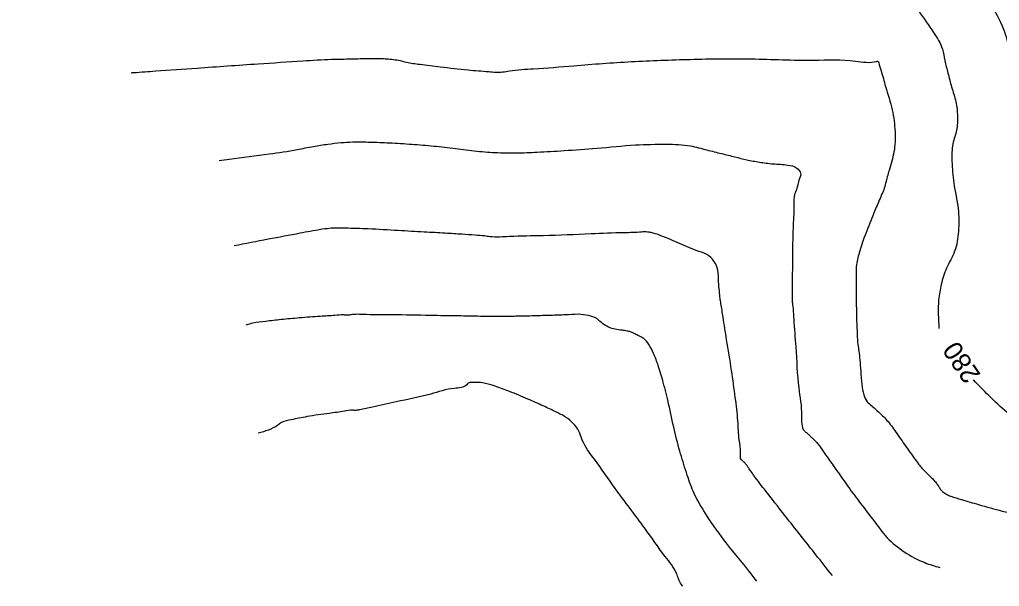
# Model space of a CAD drawing. Extents: x -478102 to -473059, y -1117705 to -1114104.
# Drawn here: x -475379.9 to -475174.1, y -1116864.7 to -1116745.7 of the extents above; entities that cross this region are included whole.
import ezdxf

# ---------------------------------------------------------------- set-up
doc = ezdxf.new("R2010")
doc.units = 0
for name, color, linetype in [('Vrstevnice_hlavni', 7, 'Continuous'), ('Vrstevnice_popis', 7, 'Continuous'), ('Vrstevnice_vedlejsi', 7, 'Continuous')]:
    doc.layers.add(name, color=color, linetype=linetype)

msp = doc.modelspace()

# ---------------------------------------------------------------- linework, layer by layer
at = {"layer": 'Vrstevnice_hlavni'}
for points in [[(-475358.768, -1116741.356), (-475356.711, -1116740.135), (-475352.511, -1116739.455), (-475345.14, -1116738.707), (-475334.598, -1116737.89), (-475327.036, -1116737.27), (-475322.455, -1116736.846), (-475320.855, -1116736.618), (-475319.542, -1116736.519), (-475318.516, -1116736.548), (-475317.776, -1116736.705), (-475315.973, -1116736.853), (-475313.107, -1116736.991), (-475309.177, -1116737.119), (-475304.857, -1116737.63), (-475300.147, -1116738.524), (-475295.047, -1116739.801), (-475290.514, -1116740.779), (-475286.548, -1116741.458), (-475283.15, -1116741.838), (-475278.27, -1116741.681), (-475271.909, -1116740.985), (-475264.066, -1116739.751), (-475256.944, -1116738.794), (-475250.543, -1116738.116), (-475244.862, -1116737.714), (-475239.016, -1116737.489), (-475233.004, -1116737.442), (-475226.827, -1116737.571), (-475220.399, -1116737.105), (-475213.723, -1116736.045), (-475206.796, -1116734.39), (-475200.704, -1116735.146), (-475195.447, -1116738.313), (-475191.025, -1116743.89), (-475187.9, -1116748.412), (-475186.073, -1116751.876), (-475185.543, -1116754.284), (-475184.893, -1116756.934), (-475184.122, -1116759.824), (-475183.231, -1116762.956), (-475182.889, -1116765.987), (-475183.096, -1116768.918), (-475183.853, -1116771.747), (-475184.048, -1116775.433), (-475183.681, -1116779.975), (-475182.751, -1116785.373), (-475182.693, -1116790.16), (-475183.506, -1116794.333), (-475185.19, -1116797.895), (-475186.303, -1116801.281), (-475186.846, -1116804.493), (-475186.791, -1116810.568)], [(-475240.627, -1116864.663), (-475240.877, -1116864.261), (-475241.474, -1116863.11), (-475241.915, -1116861.944), (-475244.28, -1116858.392), (-475248.569, -1116852.455), (-475254.782, -1116844.132), (-475259.162, -1116837.963), (-475261.708, -1116833.946), (-475262.421, -1116832.082), (-475263.583, -1116830.477), (-475265.193, -1116829.129), (-475267.253, -1116828.04), (-475269.903, -1116826.78), (-475273.143, -1116825.349), (-475276.975, -1116823.747), (-475280.033, -1116822.629), (-475282.318, -1116821.995), (-475283.831, -1116821.845), (-475284.941, -1116821.853), (-475285.647, -1116822.019), (-475285.951, -1116822.343), (-475288.578, -1116823.103), (-475293.529, -1116824.298), (-475300.804, -1116825.929), (-475305.786, -1116827.036), (-475308.475, -1116827.62), (-475308.87, -1116827.681), (-475309.242, -1116827.712), (-475309.59, -1116827.712), (-475309.914, -1116827.682), (-475311.671, -1116827.892), (-475314.861, -1116828.344), (-475319.483, -1116829.037), (-475322.825, -1116829.686), (-475324.887, -1116830.289), (-475325.669, -1116830.847), (-475329.759, -1116832.513)], [(-475165.151, -1116831.586), (-475166.683, -1116831.906), (-475168.964, -1116830.907), (-475171.993, -1116828.59), (-475179.549, -1116821.317)]]:
    msp.add_spline(points, degree=3, dxfattribs=at)
at = {"layer": 'Vrstevnice_vedlejsi'}
for points in [[(-475317.402, -1116697.311), (-475317.363, -1116697.318), (-475316.603, -1116697.461), (-475315.123, -1116697.741), (-475312.92, -1116698.158), (-475311.368, -1116698.443), (-475310.465, -1116698.595), (-475310.211, -1116698.614), (-475309.863, -1116698.624), (-475309.421, -1116698.624), (-475308.884, -1116698.614), (-475308.515, -1116698.664), (-475308.313, -1116698.772), (-475308.278, -1116698.939), (-475308.258, -1116699.23), (-475308.253, -1116699.645), (-475308.262, -1116700.184), (-475308.28, -1116700.605), (-475308.307, -1116700.906), (-475308.342, -1116701.089), (-475308.4, -1116701.257), (-475308.48, -1116701.41), (-475308.582, -1116701.549), (-475308.36, -1116701.763), (-475307.813, -1116702.053), (-475306.941, -1116702.417), (-475305.165, -1116702.522), (-475302.486, -1116702.367), (-475298.904, -1116701.952), (-475295.98, -1116701.58), (-475293.714, -1116701.252), (-475292.107, -1116700.966), (-475290.151, -1116700.632), (-475287.845, -1116700.251), (-475285.19, -1116699.821), (-475283.467, -1116699.685), (-475282.678, -1116699.841), (-475282.82, -1116700.289), (-475282.893, -1116700.598), (-475282.897, -1116700.766), (-475282.83, -1116700.795), (-475282.522, -1116701.008), (-475281.973, -1116701.407), (-475281.183, -1116701.991), (-475279.14, -1116702.532), (-475275.844, -1116703.031), (-475271.295, -1116703.488), (-475267.025, -1116703.455), (-475263.034, -1116702.933), (-475259.323, -1116701.922), (-475255.577, -1116701.148), (-475251.797, -1116700.612), (-475247.981, -1116700.314), (-475244.648, -1116700.178), (-475241.797, -1116700.205), (-475239.43, -1116700.396), (-475236.373, -1116700.194), (-475232.627, -1116699.601), (-475228.192, -1116698.615), (-475224.557, -1116697.628), (-475221.724, -1116696.639), (-475219.691, -1116695.649), (-475215.891, -1116694.546), (-475210.322, -1116693.329), (-475202.985, -1116691.999), (-475196.288, -1116692.148), (-475190.231, -1116693.775), (-475184.814, -1116696.881), (-475179.571, -1116702.762), (-475174.503, -1116711.419), (-475169.608, -1116722.851), (-475165.925, -1116731.003), (-475163.453, -1116735.874), (-475162.192, -1116737.464), (-475161.091, -1116739.704), (-475160.152, -1116742.593), (-475159.374, -1116746.131), (-475155.571, -1116749.024), (-475148.745, -1116751.271), (-475138.894, -1116752.873), (-475131.322, -1116754.29), (-475126.028, -1116755.521), (-475123.014, -1116756.568), (-475119.062, -1116755.588), (-475114.17, -1116752.58), (-475108.341, -1116747.546), (-475101.953, -1116742.021), (-475095.007, -1116736.008), (-475087.504, -1116729.505), (-475082.315, -1116724.914), (-475079.441, -1116722.237), (-475078.882, -1116721.473), (-475078.472, -1116720.916), (-475078.209, -1116720.564), (-475078.094, -1116720.42), (-475077.919, -1116720.217), (-475077.682, -1116719.958)], [(-475170.121, -1116764.984), (-475169.8, -1116763.784), (-475169.712, -1116762.54), (-475169.857, -1116761.254), (-475170.235, -1116759.926), (-475170.837, -1116757.447), (-475171.664, -1116753.818), (-475172.715, -1116749.04), (-475175.186, -1116743.622), (-475179.076, -1116737.565), (-475184.386, -1116730.868), (-475188.402, -1116725.291), (-475191.125, -1116720.833), (-475192.554, -1116717.494), (-475194.034, -1116714.966), (-475195.565, -1116713.248), (-475197.147, -1116712.341), (-475198.916, -1116711.866), (-475200.872, -1116711.823), (-475203.014, -1116712.211), (-475204.641, -1116712.566), (-475205.751, -1116712.889), (-475206.344, -1116713.178), (-475210.286, -1116714.159), (-475217.576, -1116715.832), (-475228.214, -1116718.196), (-475235.384, -1116719.766), (-475239.087, -1116720.542), (-475239.321, -1116720.523), (-475239.604, -1116720.52), (-475239.934, -1116720.534), (-475240.312, -1116720.563), (-475241.346, -1116720.796), (-475243.034, -1116721.231), (-475245.377, -1116721.87), (-475250.485, -1116722.853), (-475258.355, -1116724.181), (-475268.989, -1116725.854), (-475276.404, -1116726.933), (-475280.601, -1116727.418), (-475281.579, -1116727.309), (-475284.618, -1116726.638), (-475289.718, -1116725.406), (-475296.879, -1116723.612), (-475302.033, -1116722.16), (-475305.179, -1116721.047), (-475306.317, -1116720.275), (-475307.319, -1116719.765), (-475308.185, -1116719.516), (-475308.915, -1116719.529), (-475309.573, -1116719.541), (-475310.158, -1116719.551), (-475310.672, -1116719.56), (-475311.391, -1116719.475), (-475312.315, -1116719.296), (-475313.445, -1116719.023), (-475314.897, -1116718.607), (-475316.672, -1116718.049), (-475318.771, -1116717.347), (-475320.622, -1116716.843), (-475322.226, -1116716.537), (-475323.583, -1116716.429), (-475324.786, -1116716.347), (-475325.835, -1116716.29), (-475326.73, -1116716.258), (-475327.815, -1116716.32), (-475329.091, -1116716.474), (-475330.557, -1116716.722), (-475332.477, -1116716.954), (-475334.853, -1116717.17), (-475337.682, -1116717.371), (-475340.299, -1116717.935), (-475342.703, -1116718.861), (-475344.894, -1116720.15), (-475346.644, -1116721.05), (-475347.951, -1116721.561), (-475348.817, -1116721.685), (-475349.838, -1116721.801), (-475351.014, -1116721.911), (-475352.345, -1116722.014), (-475354.025, -1116722.554), (-475356.054, -1116723.529), (-475358.432, -1116724.942), (-475360.515, -1116725.742), (-475362.303, -1116725.931), (-475363.797, -1116725.507), (-475365.618, -1116725.458), (-475367.766, -1116725.784), (-475370.241, -1116726.484), (-475373.444, -1116727.274), (-475377.376, -1116728.152), (-475379.893, -1116728.678)], [(-475198.872, -1116782.448), (-475198.889, -1116782.522), (-475199.479, -1116783.99), (-475200.641, -1116786.852), (-475202.376, -1116791.109), (-475203.546, -1116794.658), (-475204.149, -1116797.501), (-475204.186, -1116799.637), (-475204.186, -1116802.254), (-475204.15, -1116805.35), (-475204.078, -1116808.926), (-475203.963, -1116811.773), (-475203.807, -1116813.889), (-475203.609, -1116815.275), (-475203.409, -1116817.139), (-475203.206, -1116819.479), (-475203.002, -1116822.297), (-475202.549, -1116824.448), (-475201.849, -1116825.933), (-475200.9, -1116826.752), (-475199.97, -1116827.585), (-475199.06, -1116828.434), (-475198.169, -1116829.297), (-475197.248, -1116830.346), (-475196.299, -1116831.582), (-475195.321, -1116833.003), (-475194.276, -1116834.502), (-475193.164, -1116836.08), (-475191.987, -1116837.736), (-475191.048, -1116838.997), (-475190.348, -1116839.862), (-475189.887, -1116840.331), (-475189.342, -1116840.882), (-475188.711, -1116841.515), (-475187.995, -1116842.229), (-475187.387, -1116842.924), (-475186.887, -1116843.599), (-475186.494, -1116844.254), (-475185.936, -1116844.825), (-475185.21, -1116845.312), (-475184.318, -1116845.714), (-475182.066, -1116846.437), (-475178.453, -1116847.482), (-475173.48, -1116848.848), (-475168.095, -1116850.137), (-475162.299, -1116851.348), (-475156.09, -1116852.483), (-475151.557, -1116853.176), (-475148.699, -1116853.429), (-475147.516, -1116853.242), (-475143.339, -1116852.01), (-475136.167, -1116849.732), (-475126.002, -1116846.41), (-475118.467, -1116843.633), (-475113.565, -1116841.403), (-475111.294, -1116839.72), (-475109.309, -1116838.361), (-475107.61, -1116837.328), (-475106.196, -1116836.62), (-475105.185, -1116836.124), (-475104.579, -1116835.84), (-475104.376, -1116835.769), (-475103.967, -1116835.487), (-475103.352, -1116834.994), (-475102.532, -1116834.29), (-475101.427, -1116833.181), (-475100.036, -1116831.668), (-475098.361, -1116829.749), (-475095.9, -1116826.559), (-475092.654, -1116822.096), (-475088.623, -1116816.362), (-475085.413, -1116811.688), (-475083.026, -1116808.074), (-475081.461, -1116805.521), (-475080.33, -1116803.693), (-475079.634, -1116802.592), (-475079.372, -1116802.217), (-475079.018, -1116801.768), (-475078.571, -1116801.243), (-475078.032, -1116800.644), (-475076.447, -1116798.296), (-475073.814, -1116794.198), (-475070.135, -1116788.35), (-475066.815, -1116782.805), (-475063.856, -1116777.563), (-475061.256, -1116772.623), (-475059.121, -1116768.656), (-475057.452, -1116765.661), (-475056.247, -1116763.638), (-475054.911, -1116761.508), (-475053.445, -1116759.27), (-475051.847, -1116756.925), (-475050.593, -1116755.098), (-475049.682, -1116753.789), (-475049.114, -1116752.999), (-475048.622, -1116752.397), (-475048.207, -1116751.982)], [(-475356.437, -1116756.85), (-475356.402, -1116756.847), (-475355.899, -1116756.809), (-475351.297, -1116756.484), (-475342.598, -1116755.871), (-475329.8, -1116754.971), (-475320.393, -1116754.354), (-475314.376, -1116754.02), (-475311.75, -1116753.969), (-475309.616, -1116753.924), (-475307.973, -1116753.886), (-475306.823, -1116753.855), (-475305.569, -1116753.85), (-475304.212, -1116753.872), (-475302.751, -1116753.919), (-475301.338, -1116754.061), (-475299.973, -1116754.297), (-475298.655, -1116754.627), (-475295.836, -1116755.064), (-475291.518, -1116755.608), (-475285.699, -1116756.259), (-475281.336, -1116756.617), (-475278.427, -1116756.681), (-475276.974, -1116756.452), (-475271.984, -1116756.016), (-475263.457, -1116755.371), (-475251.394, -1116754.519), (-475238.98, -1116754.042), (-475226.213, -1116753.94), (-475213.094, -1116754.215), (-475204.311, -1116754.389), (-475199.866, -1116754.463), (-475199.757, -1116754.437), (-475199.661, -1116754.449), (-475199.578, -1116754.499), (-475199.508, -1116754.587), (-475199.459, -1116754.658), (-475199.43, -1116754.713), (-475199.422, -1116754.751), (-475198.948, -1116756.421), (-475198.009, -1116759.723), (-475196.605, -1116764.658), (-475196.014, -1116769.239), (-475196.236, -1116773.466), (-475197.272, -1116777.34), (-475197.992, -1116780.008), (-475198.395, -1116781.472), (-475198.481, -1116781.731), (-475198.554, -1116781.931), (-475198.616, -1116782.072), (-475198.665, -1116782.153), (-475198.713, -1116782.222), (-475198.761, -1116782.28), (-475198.808, -1116782.327), (-475198.844, -1116782.383), (-475198.872, -1116782.448)], [(-475337.977, -1116775.276), (-475335.865, -1116775.004), (-475327.465, -1116773.876), (-475321.573, -1116772.98), (-475318.187, -1116772.317), (-475315.115, -1116771.831), (-475312.358, -1116771.521), (-475309.914, -1116771.389), (-475306.723, -1116771.394), (-475302.783, -1116771.535), (-475298.096, -1116771.813), (-475293.474, -1116772.192), (-475288.918, -1116772.672), (-475284.427, -1116773.252), (-475279.971, -1116773.587), (-475275.551, -1116773.676), (-475271.165, -1116773.52), (-475265.536, -1116773.191), (-475258.662, -1116772.691), (-475250.544, -1116772.018), (-475243.985, -1116771.854), (-475238.986, -1116772.197), (-475235.546, -1116773.048), (-475232.429, -1116773.819), (-475229.635, -1116774.51), (-475227.163, -1116775.119), (-475224.493, -1116775.607), (-475221.624, -1116775.973), (-475218.558, -1116776.217), (-475216.628, -1116776.875), (-475215.836, -1116777.945), (-475216.182, -1116779.429), (-475216.501, -1116780.635), (-475216.793, -1116781.562), (-475217.057, -1116782.212), (-475217.272, -1116784.831), (-475217.436, -1116789.419), (-475217.549, -1116795.978), (-475217.619, -1116800.616), (-475217.646, -1116803.333), (-475217.63, -1116804.129), (-475217.605, -1116804.763), (-475217.57, -1116805.235), (-475217.526, -1116805.543), (-475217.289, -1116808.603), (-475216.86, -1116814.413), (-475216.239, -1116822.975), (-475215.636, -1116828.845), (-475215.053, -1116832.023), (-475214.489, -1116832.51), (-475213.937, -1116833.005), (-475213.395, -1116833.51), (-475212.866, -1116834.023), (-475212.318, -1116834.647), (-475211.754, -1116835.381), (-475211.172, -1116836.226), (-475209.989, -1116837.907), (-475208.205, -1116840.425), (-475205.82, -1116843.779), (-475203.267, -1116847.234), (-475200.547, -1116850.789), (-475197.658, -1116854.446), (-475194.069, -1116857.41), (-475189.778, -1116859.681), (-475186.615, -1116860.694)], [(-475286.951, -1116790.758), (-475290.476, -1116790.549), (-475294.938, -1116790.292), (-475300.34, -1116789.989), (-475306.679, -1116789.639), (-475311.518, -1116789.488), (-475314.859, -1116789.538), (-475316.699, -1116789.788), (-475320.982, -1116790.545), (-475327.706, -1116791.809), (-475334.818, -1116793.185)], [(-475209.17, -1116862.397), (-475212.628, -1116858.028), (-475218.596, -1116850.472), (-475222.828, -1116845.079), (-475225.323, -1116841.85), (-475226.081, -1116840.784), (-475226.648, -1116839.983), (-475227.024, -1116839.449), (-475227.209, -1116839.18), (-475227.388, -1116838.947), (-475227.562, -1116838.749), (-475227.731, -1116838.586), (-475227.903, -1116838.425), (-475228.078, -1116838.268), (-475228.258, -1116838.113), (-475228.475, -1116836.666), (-475228.73, -1116833.926), (-475229.022, -1116829.893), (-475229.561, -1116825.037), (-475230.346, -1116819.357), (-475231.377, -1116812.854), (-475232.121, -1116808.164), (-475232.577, -1116805.286), (-475232.746, -1116804.221), (-475232.908, -1116802.699), (-475233.065, -1116800.719), (-475233.216, -1116798.283), (-475234.047, -1116796.377), (-475235.558, -1116795.001), (-475237.751, -1116794.154), (-475239.829, -1116793.317), (-475241.793, -1116792.489), (-475243.644, -1116791.669), (-475245.17, -1116791.051), (-475246.372, -1116790.633), (-475247.249, -1116790.416), (-475248.018, -1116790.286), (-475248.678, -1116790.244), (-475249.23, -1116790.29), (-475252.953, -1116790.44), (-475259.845, -1116790.695), (-475269.908, -1116791.054), (-475277, -1116791.244), (-475281.122, -1116791.265), (-475282.274, -1116791.116), (-475284.217, -1116790.947), (-475286.951, -1116790.758)], [(-475225.006, -1116863.573), (-475226.125, -1116862.122), (-475231.421, -1116855.596), (-475235.441, -1116849.949), (-475238.186, -1116845.181), (-475239.657, -1116841.292), (-475241.042, -1116836.864), (-475242.342, -1116831.898), (-475243.557, -1116826.393), (-475244.693, -1116821.872), (-475245.749, -1116818.334), (-475246.726, -1116815.78), (-475247.735, -1116813.888), (-475248.776, -1116812.658), (-475249.849, -1116812.09), (-475250.673, -1116811.664), (-475251.249, -1116811.381), (-475251.577, -1116811.239), (-475252.278, -1116811.079), (-475253.353, -1116810.901), (-475254.801, -1116810.704), (-475256.172, -1116810.232), (-475257.465, -1116809.485), (-475258.68, -1116808.463), (-475260.381, -1116807.821), (-475262.569, -1116807.559), (-475265.242, -1116807.678), (-475268.311, -1116807.788), (-475271.775, -1116807.888), (-475275.636, -1116807.979), (-475278.895, -1116808.024), (-475281.554, -1116808.022), (-475283.613, -1116807.974), (-475287.637, -1116807.903), (-475293.626, -1116807.807), (-475301.58, -1116807.687), (-475307.037, -1116807.627), (-475309.995, -1116807.629), (-475310.456, -1116807.691), (-475310.924, -1116807.722), (-475311.4, -1116807.721), (-475311.883, -1116807.689), (-475313.667, -1116807.779), (-475316.752, -1116807.99), (-475321.138, -1116808.322), (-475324.955, -1116808.673), (-475328.205, -1116809.042), (-475330.887, -1116809.43), (-475332.339, -1116809.807)]]:
    msp.add_spline(points, degree=3, dxfattribs=at)

# ---------------------------------------------------------------- texts
at = {"layer": 'Vrstevnice_popis'}
msp.add_text(' 280 ', height=4, rotation=124.25281, dxfattribs=at).set_placement((-475177.063, -1116821.467))

doc.saveas('drawing.dxf')
